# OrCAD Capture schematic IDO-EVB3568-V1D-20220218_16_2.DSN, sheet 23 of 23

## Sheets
23 P17. WIFI/BT-SDMMC1_1T1R + UART: size A3; note: WIFI/BT-SDMMC1_1T1R + UART
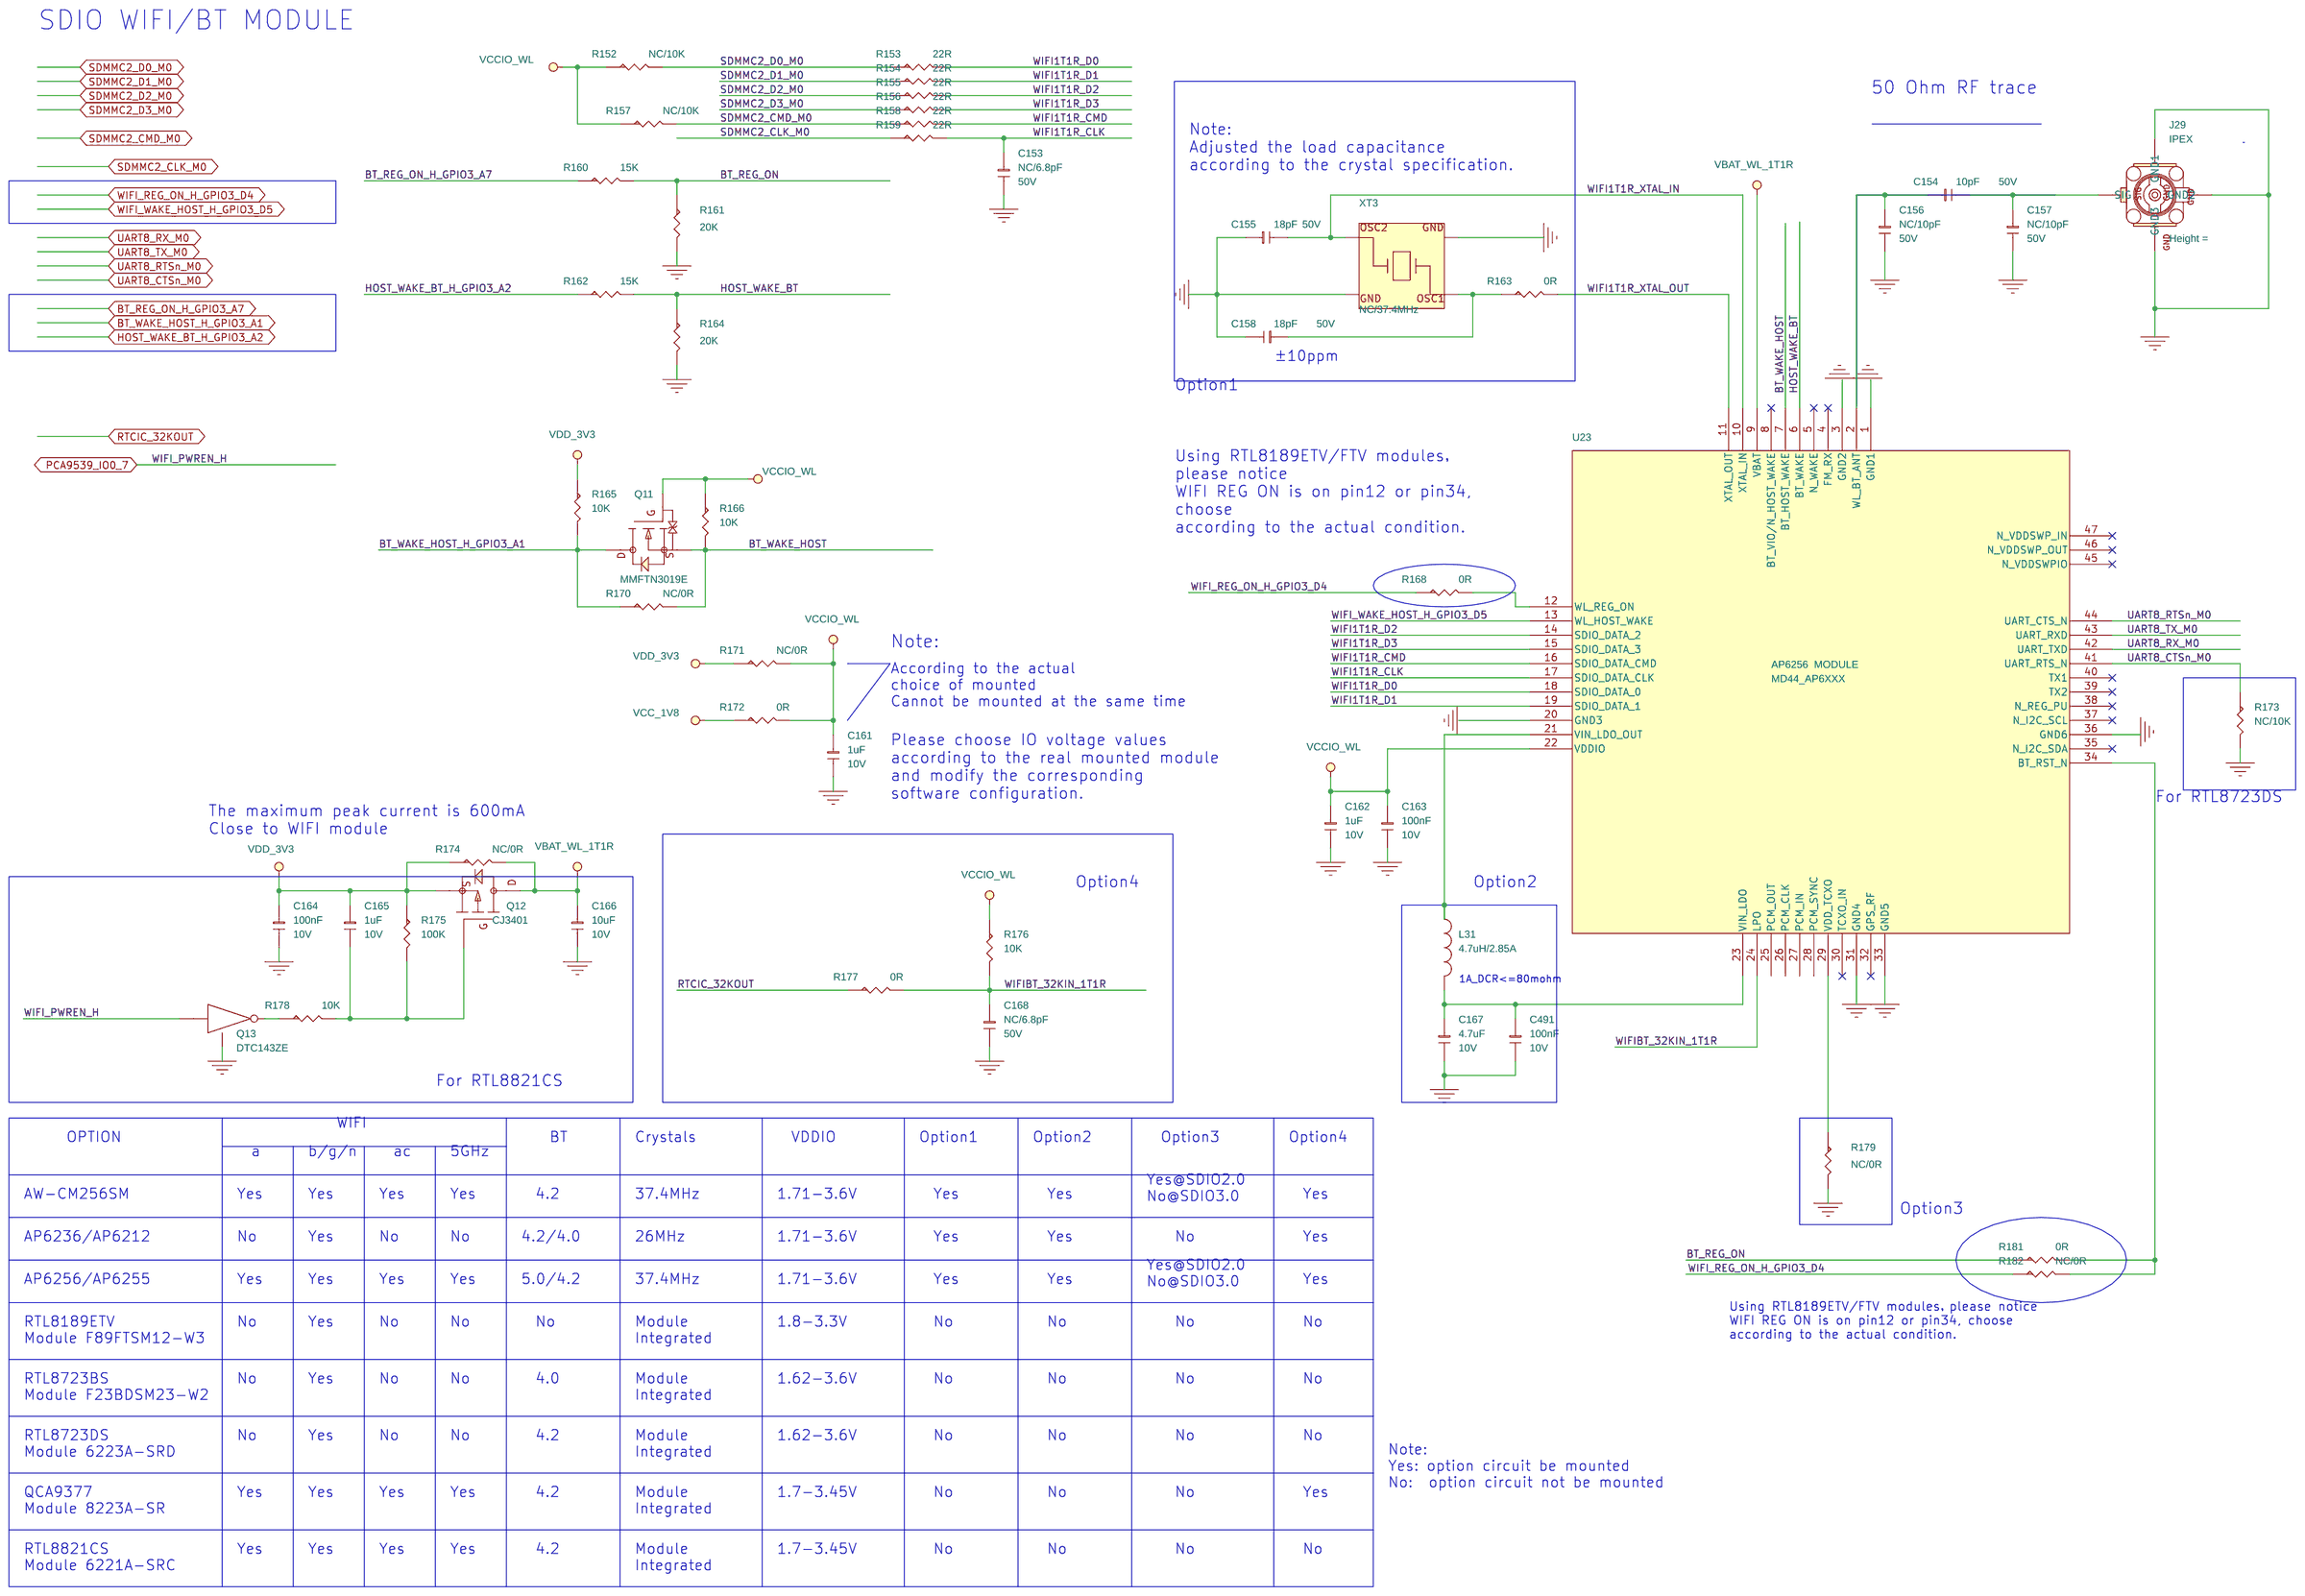
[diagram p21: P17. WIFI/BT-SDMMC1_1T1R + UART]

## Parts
C153  NC/6.8pF  [C0402L]
C154  10pF  [C0402L]
C155  18pF  [C0402L]
C156  NC/10pF  [C0402L]
C157  NC/10pF  [C0402L]
C158  18pF  [C0402L]
C161  1uF  [C0402L]
C162  1uF  [C0402L]
C163  100nF  [C0402L]
C164  100nF  [C0402L]
C165  1uF  [C0402L]
C166  10uF  [C0603L]
C167  4.7uF  [C0402L]
C168  NC/6.8pF  [C0402L]
C491  100nF  [C0402L]
J29  IPEX  [IPEX-20279-001E]
L31  4.7uH/2.85A  [L4040]
Q11  MMFTN3019E  [SOT523]
Q12  CJ3401  [SOT23]
Q13  DTC143ZE  [SOT523]
R152  NC/10K  [R0402L]
R153  22R  [R0402L]
R154  22R  [R0402L]
R155  22R  [R0402L]
R156  22R  [R0402L]
R157  NC/10K  [R0402L]
R158  22R  [R0402L]
R159  22R  [R0402L]
R160  15K  [R0402L]
R161  20K  [R0402L]
R162  15K  [R0402L]
R163  0R  [R0402L]
R164  20K  [R0402L]
R165  10K  [R0402L]
R166  10K  [R0402L]
R168  0R  [R0402L]
R170  NC/0R  [R0402L]
R171  NC/0R  [R0402L]
R172  0R  [R0402L]
R173  NC/10K  [R0402L]
R174  NC/0R  [R0805L]
R175  100K  [R0402L]
R176  10K  [R0402L]
R177  0R  [R0402L]
R178  10K  [R0402L]
R179  NC/0R  [R0402L]
R181  0R  [R0402L]
R182  NC/0R  [R0402L]
U23  AP6256  MODULE  [MD44_AP6XXX]
XT3  NC/37.4MHz  [xtal_32x25_4p]

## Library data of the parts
C153 C168 = C-0402: DSC1: ±0.25PF; DSC2: 50V; DSC3: C0G; ERP Number: 1010200056; ID: 18; Manufacture: 三星|国巨|村田; Part Name: 贴片电容; Part Number: C020102120018; Price: 0.01
C154 C156 C157 = C-0402: DSC1: ±5%; DSC2: 50V; DSC3: C0G; ERP Number: 1010200151; ID: 21; Manufacture: 三星|国巨|村田; Part Name: 贴片电容; Part Number: C020102120021; Price: 0.01
C155 C158 = C-0402: DSC1: ±5%; DSC2: 50V; DSC3: C0G; ERP Number: 1010200091; ID: 27; Manufacture: 三星|国巨|村田; Part Name: 贴片电容; Part Number: C020102120027; Price: 0.02
C161 C162 C165 = C-0402: DSC1: ±10%; DSC2: 10V; DSC3: X5R; ERP Number: 1010200054; ID: 64; Manufacture: 三星|国巨|村田; Part Name: 贴片电容; Part Number: C020102120064; Price: 0.02
C163 C164 C491 = C-0402: DSC1: ±10%; DSC2: 10V; DSC3: X7R; ID: 60; Manufacture: 三星|国巨|村田; Part Name: 贴片电容; Part Number: C020102120060; Price: 0.01
C166 = C-0603: DSC1: ±20%; DSC2: 10V; DSC3: X5R; ERP Number: 1010200076; ID: 71; Manufacture: 三星|国巨|村田; Part Name: 贴片电容; Part Number: C020102120071; Price: 0.05
C167 = C-0402: DSC1: ±20%; DSC2: 10V; DSC3: X5R; ID: 67; Manufacture: 三星|国巨|村田; Part Name: 贴片电容; Part Number: C020102120067; Price: 0.04
J29 = RF-IPEX-20279: DSC1: IPEX-20279-001E-01 板端贴片天线座 U.LF接头; DSC2: 贴片; ID: 1; Part Name: IPEX座; Part Number: J110103040001
L31 = L-IND: DSC1: ±20%; DSC2: Isat=4.0A; DSC3: Irms=2.85A; DSC4: 108mΩ; DSC5: 4.0*4.0*2.0mm; DSC6: WPN4020H4R7MT(顺络); ERP Number: 1010200405; Manufacture: 顺络; Part Name: 功率电感; Part Number: C060202340021; Price: 0.3
Q11 = N-MOS-Q: DSC1: Vds=30V; DSC2: Id=100mA; DSC3: Vgs(th)=1.5V; DSC4: Vgs=±20V; DSC5: pd=150mW; ERP Number: 1010800011; ID: 4; Manufacture: 先科; Part Name: N-MOS; Part Number: C030202190004; Price: 0.1
Q12 = P-MOS: DSC1: Vds=-30V; DSC2: Id=-4.2A; DSC3: Vgs(th)=1.3V; DSC4: Vgs=±12V; DSC5: pd=350mW; ERP Number: 1010800001; ID: 1; Manufacture: 长电; Part Number: C030202190001; Price: 0.17
Q13 = S-NPN: DSC1: 数字三极管,NPN - 预偏压,Ic=100mA; ERP Number: 0; ID: 2; LC Number: C78593; Manufacture: CJ江苏长电; Part Number: BJ00G1100000; Price: 0.07; Type Name: 数字三极管
R152 R157 R165 R166 R173 R176 R178 = R-0402: DSC1: ±1%; DSC2: 1/16W; ERP Number: 1010200140; ID: 856; Part Name: 贴片电阻; Part Number: C011002080856; Price: 0.01
R153-R156 R158 R159 = R-0402: DSC1: ±1%; DSC2: 1/16W; ID: 552; Part Name: 贴片电阻; Part Number: C011002080552; Price: 0.01
R160 R162 = R-0402: DSC1: ±1%; DSC2: 1/16W; ERP Number: 1010200458; ID: 875; Part Name: 贴片电阻; Part Number: C011002080875; Price: 0.01
R161 R164 = R-0402: DSC1: ±1%; DSC2: 1/16W; ERP Number: 1010200333; ID: 889; Part Name: 贴片电阻; Part Number: C011002080889; Price: 0.01
R163 R168 R170-R172 R177 R179 R181 R182 = R-0402: DSC1: ±1%; DSC2: 1/16W; ID: 413; Part Name: 贴片电阻; Part Number: C011002080413; Price: 0.01
R174 = R-0805: DSC1: ±1%; DSC2: 1/8W; ERP Number: 1010200199; ID: 1,448; Part Name: 贴片电阻; Part Number: C011002081448; Price: 0.01
R175 = R-0402: DSC1: ±1%; DSC2: 1/16W; ERP Number: 1010200137; ID: 976; Part Name: 贴片电阻; Part Number: C011002080976; Price: 0.01
U23 = MODULE_AP6XXX: WiFi+Bluetooth 4.0(HS)+FM Rx; Created by: JJJ; Manufacturer: Ampak（正基科技）; Manufacturer PN: AP6335; Part Type: module; Priority: A; RK PN: AP6335
XT3 = XTAL-4P: DSC1: 60Ω; DSC2: ±10ppm; DSC3: 12pF; DSC4: -40℃~+85℃; DSC5: 3.2*2.5mm 4P; ID: 13; Manufacture: 爱普生; Part Name: 贴片无源晶振

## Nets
GND: C153.1 C155.2 C156.1 C157.1 C158.1 C161.1 C162.1 C163.1 C164.1 C166.1 C167.1 C168.1 C491.1 J29.1(GND1) J29.3(GND2) J29.4(GND3) Q13.2 R161.2 R164.2 R173.2 R179.2 U23.1(GND1) U23.3(GND2) U23.20(GND3) U23.31(GND4) U23.33(GND5) U23.36(GND6) XT3.2 XT3.4 ; also on sheet 4 5 6 7 8 9 10 11 12 13 14 15 16 17 18 19 20 21 22
VBAT_WL_1T1R: C166.2 Q12.3(DRAIN) R174.2 U23.9(VBAT)
VCC_1V8: R172.1 ; also on sheet 5 13 14 15 16 21
VCCIO_WL: C161.2 C162.2 C163.2 Q11.1(GATE) R152.1 R157.1 R166.1 R171.2 R172.2 R176.1 U23.22(VDDIO) ; also on sheet 22
VDD_3V3: C164.2 C165.2 Q12.2(SOURCE) R165.1 R171.1 R174.1 R175.1 ; also on sheet 4 6 7 8 9 10 11 12 13 14 15 16 17 18 22
BT_REG_ON: R160.2 R161.1 R181.1
BT_REG_ON_H_GPIO3_A7: R160.1 ; also on sheet 5
BT_WAKE_HOST: Q11.2(SOURCE) R166.2 R170.2 U23.7(BT_HOST_WAKE)
BT_WAKE_HOST_H_GPIO3_A1: Q11.3(DRAIN) R165.2 R170.1 ; also on sheet 5
HOST_WAKE_BT: R162.2 R164.1 U23.6(BT_WAKE)
HOST_WAKE_BT_H_GPIO3_A2: R162.1 ; also on sheet 5
PCA9539_IO0_7: Q13.1 ; also on sheet 17
RTCIC_32KOUT: R177.1 ; also on sheet 18
SDMMC2_CLK_M0: R159.1 ; also on sheet 5
SDMMC2_CMD_M0: R157.2 R158.1 ; also on sheet 5
SDMMC2_D0_M0: R152.2 R153.1 ; also on sheet 5
SDMMC2_D1_M0: R154.1 ; also on sheet 5
SDMMC2_D2_M0: R155.1 ; also on sheet 5
SDMMC2_D3_M0: R156.1 ; also on sheet 5
UART8_CTSn_M0: R173.1 U23.41(UART_RTS_N) ; also on sheet 5
UART8_RTSn_M0: U23.44(UART_CTS_N) ; also on sheet 5
UART8_RX_M0: U23.42(UART_TXD) ; also on sheet 5
UART8_TX_M0: U23.43(UART_RXD) ; also on sheet 5
WIFI1T1R_CLK: C153.2 R159.2 U23.17(SDIO_DATA_CLK)
WIFI1T1R_CMD: R158.2 U23.16(SDIO_DATA_CMD)
WIFI1T1R_D0: R153.2 U23.18(SDIO_DATA_0)
WIFI1T1R_D1: R154.2 U23.19(SDIO_DATA_1)
WIFI1T1R_D2: R155.2 U23.14(SDIO_DATA_2)
WIFI1T1R_D3: R156.2 U23.15(SDIO_DATA_3)
WIFI1T1R_XTAL_IN: C155.1 U23.10(XTAL_IN) XT3.3
WIFI1T1R_XTAL_OUT: R163.2 U23.11(XTAL_OUT)
WIFI_REG_ON_H_GPIO3_D4: R168.1 R182.1 ; also on sheet 5
WIFI_WAKE_HOST_H_GPIO3_D5: U23.13(WL_HOST_WAKE) ; also on sheet 5
WIFIBT_32KIN_1T1R: C168.2 R176.2 R177.2 U23.24(LPO)
N17052705: R179.1 U23.29(VDD_TCXO)
N17052995: R181.2 R182.2 U23.34(BT_RST_N)
N17053074: C154.2 C156.2 U23.2(WL_BT_ANT)
N17053234: C154.1 C157.2 J29.2(SIG)
N17053342: C167.2 C491.2 L31.2 U23.23(VIN_LDO)
N17053374: C158.2 R163.1 XT3.1
N17053434: L31.1 U23.21(VIN_LDO_OUT)
N68610828: C165.1 Q12.1(GATE) R175.2 R178.2
N68611164: Q13.3 R178.1
N68644173: R168.2 U23.12(WL_REG_ON)

Not connected (* = marked no-connect by the designer): U23 4(FM_RX)* 5(N_WAKE)* 8(BT_VIO/N_HOST_WAKE)* 25(PCM_OUT) 26(PCM_CLK) 27(PCM_IN) 28(PCM_SYNC) 30(TCXO_IN)* 32(GPS_RF)* 35(N_I2C_SDA)* 37(N_I2C_SCL)* 38(N_REG_PU)* 39(TX2)* 40(TX1)* 45(N_VDDSWPIO)* 46(N_VDDSWP_OUT)* 47(N_VDDSWP_IN)*

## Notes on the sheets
sheet 23
- SDIO WIFI/BT MODULE
- 50 Ohm RF trace
- Note:
  Adjusted the load capacitance
  according to the crystal specification.
- ±10ppm
- Option1
- Using RTL8189ETV/FTV modules，
  please notice
  WIFI REG ON is on pin12 or pin34,
  choose
  according to the actual condition.
- Note:
- According to the actual
  choice of mounted
  Cannot be mounted at the same time
- Please choose IO voltage values
  according to the real mounted module
  and modify the corresponding
  software configuration.
- The maximum peak current is 600mA
  Close to WIFI module
- For RTL8723DS
- Option4
- Option2
- 1A_DCR<=80mohm
- For RTL8821CS
- WIFI
- OPTION
- BT
- Crystals
- VDDIO
- Option1
- Option2
- Option3
- Option4
- a
- b/g/n
- ac
- 5GHz
- AW-CM256SM
- Yes
- Yes
- Yes
- Yes
- 4.2
- 37.4MHz
- 1.71-3.6V
- Yes
- Yes
- Yes@SDIO2.0
  No@SDIO3.0
- Yes
- Option3
- AP6236/AP6212
- No
- Yes
- No
- No
- 4.2/4.0
- 26MHz
- 1.71-3.6V
- Yes
- Yes
- No
- Yes
- AP6256/AP6255
- Yes
- Yes
- Yes
- Yes
- 5.0/4.2
- 37.4MHz
- 1.71-3.6V
- Yes
- Yes
- Yes@SDIO2.0
  No@SDIO3.0
- Yes
- Using RTL8189ETV/FTV modules，please notice
  WIFI REG ON is on pin12 or pin34, choose
  according to the actual condition.
- RTL8189ETV
  Module F89FTSM12-W3
- No
- Yes
- No
- No
- No
- Module
  Integrated
- 1.8-3.3V
- No
- No
- No
- No
- RTL8723BS
  Module F23BDSM23-W2
- No
- Yes
- No
- No
- 4.0
- Module
  Integrated
- 1.62-3.6V
- No
- No
- No
- No
- RTL8723DS
  Module 6223A-SRD
- No
- Yes
- No
- No
- 4.2
- Module
  Integrated
- 1.62-3.6V
- No
- No
- No
- No
- Note:
  Yes: option circuit be mounted
  No:  option circuit not be mounted
- QCA9377
  Module 8223A-SR
- Yes
- Yes
- Yes
- Yes
- 4.2
- Module
  Integrated
- 1.7-3.45V
- No
- No
- No
- Yes
- RTL8821CS
  Module 6221A-SRC
- Yes
- Yes
- Yes
- Yes
- 4.2
- Module
  Integrated
- 1.7-3.45V
- No
- No
- No
- No
